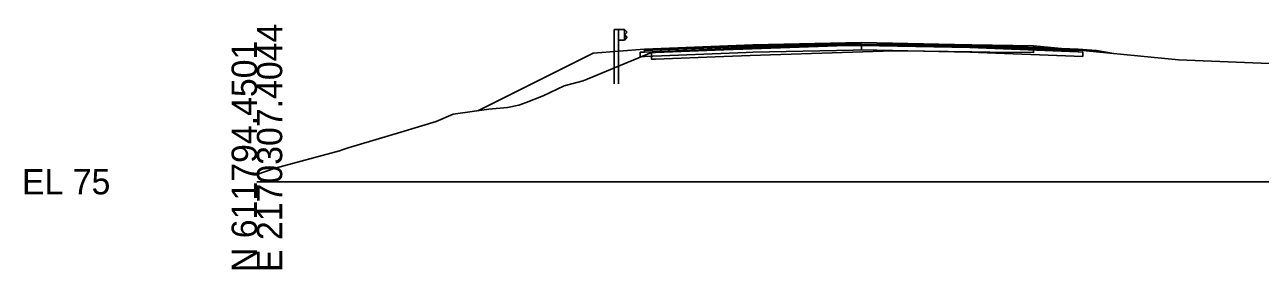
# Model space of a CAD drawing. Extents: x -26 to 1303, y -3010 to 12023.
# Drawn here: x 974.3 to 1111, y 1490.3 to 1517.4 of the extents above; entities that cross this region are included whole.
import ezdxf

# ---------------------------------------------------------------- set-up
doc = ezdxf.new("R2010")
doc.units = 0
for name, color, linetype in [('RD_GPK_XS_Cell', 7, 'Continuous'), ('RD_PD_Final_TrvlWay', 7, 'Continuous'), ('RD_XS_Base', 7, 'Continuous'), ('RD_XS_ExGround', 7, 'Continuous'), ('RD_XS_ExPaveRet', 7, 'Continuous'), ('RD_XS_GR', 7, 'Continuous'), ('RD_XS_Greenside', 7, 'Continuous'), ('RD_XS_Pave', 7, 'Continuous'), ('RD_XS_PaveOvlay_CP', 7, 'Continuous'), ('RD_XS_TieSlope', 7, 'Continuous')]:
    doc.layers.add(name, color=color, linetype=linetype)

msp = doc.modelspace()

# ---------------------------------------------------------------- linework, layer by layer
at = {"layer": 'RD_GPK_XS_Cell'}
msp.add_line((1000, 1500), (1150, 1500), dxfattribs=at)
at = {"layer": 'RD_PD_Final_TrvlWay'}
msp.add_lwpolyline([(1040.02, 1510.84), (1040.02, 1514.44), (1039.52, 1514.4), (1039.52, 1510.84)], dxfattribs=at)
at = {"layer": 'RD_XS_Base'}
for p, q in [((1054.89, 1514.84), (1054.14, 1514.81)), ((1065.98, 1515.06), (1054.89, 1514.84)), ((1066.89, 1515.08), (1065.98, 1515.06)), ((1066.89, 1515.22), (1066.89, 1515.23)), ((1066.89, 1515.23), (1066.89, 1515.18)), ((1066.89, 1515.08), (1066.89, 1515.23)), ((1066.89, 1515.23), (1066.89, 1515.23)), ((1066.89, 1515.23), (1066.89, 1515.23)), ((1066.89, 1515.23), (1066.89, 1514.58)), ((1066.89, 1515.08), (1066.89, 1515.22)), ((1066.89, 1515.18), (1066.89, 1514.58)), ((1066.89, 1515.04), (1066.89, 1515.08)), ((1066.89, 1514.58), (1066.89, 1515.08)), ((1066.89, 1515.08), (1066.89, 1515.08)), ((1066.89, 1515.08), (1066.89, 1515.08)), ((1066.89, 1515.08), (1066.89, 1515.08)), ((1078.89, 1514.84), (1066.89, 1515.08)), ((1066.89, 1514.58), (1066.89, 1515.04)), ((1090.89, 1514.36), (1078.89, 1514.84)), ((1042.86, 1514.35), (1042.39, 1514.33)), ((1042.39, 1514.33), (1042.39, 1514.31)), ((1042.39, 1514.31), (1042.39, 1513.83)), ((1042.39, 1513.83), (1042.86, 1513.85)), ((1042.89, 1514.35), (1042.86, 1514.35)), ((1042.86, 1513.85), (1042.89, 1513.85)), ((1054.14, 1514.81), (1042.89, 1514.35)), ((1042.89, 1513.85), (1054.14, 1514.31)), ((1054.14, 1514.31), (1054.89, 1514.34)), ((1054.89, 1514.34), (1065.98, 1514.56)), ((1065.98, 1514.56), (1066.89, 1514.58)), ((1066.89, 1514.58), (1066.89, 1514.58)), ((1066.89, 1514.58), (1066.89, 1514.58)), ((1066.89, 1514.58), (1078.89, 1514.34)), ((1078.89, 1514.34), (1091.39, 1513.84)), ((1080.89, 1514.76), (1080.89, 1514.76)), ((1080.89, 1514.26), (1080.89, 1514.26)), ((1091.39, 1514.34), (1090.89, 1514.36)), ((1090.89, 1514.36), (1090.89, 1514.36)), ((1091.39, 1513.84), (1091.39, 1514.34)), ((1091.39, 1514.34), (1091.39, 1514.34))]:
    msp.add_line(p, q, dxfattribs=at)
at = {"layer": 'RD_XS_ExGround'}
msp.add_lwpolyline([(1000, 1500.8), (1002.01, 1501.49), (1009.13, 1503.43), (1009.56, 1503.56), (1010.11, 1503.75), (1015.91, 1505.47), (1019.82, 1506.67), (1021.72, 1507.46), (1025.68, 1508.01), (1027.71, 1508.2), (1028.97, 1508.48), (1029.8, 1508.77), (1031.66, 1509.52), (1034.01, 1510.6), (1036.1, 1511.18), (1043.67, 1514.3), (1051.65, 1514.61), (1070.43, 1515.24), (1079.12, 1515.13), (1085.93, 1515.04), (1092.9, 1514.38), (1101.96, 1513.5), (1113.85, 1513.01)], dxfattribs=at)
at = {"layer": 'RD_XS_ExPaveRet'}
for points in [[(1085.93, 1515.04), (1085.93, 1515.04), (1085.93, 1514.89), (1085.93, 1514.29), (1085.93, 1514.29), (1085.93, 1514.29), (1081.1, 1514.35), (1079.12, 1514.38), (1071.29, 1514.48), (1070.43, 1514.49), (1054.59, 1513.96), (1051.65, 1513.86), (1044.1, 1513.56), (1043.67, 1513.55), (1043.67, 1514.22), (1043.67, 1514.3), (1044.1, 1514.31), (1051.65, 1514.61), (1054.59, 1514.71), (1070.43, 1515.24), (1071.29, 1515.23), (1079.12, 1515.13), (1081.1, 1515.1), (1085.93, 1515.04), (1085.93, 1515.04)], [(1081.1, 1515.1), (1079.12, 1515.13), (1071.29, 1515.23), (1070.43, 1515.24), (1054.59, 1514.71), (1051.65, 1514.61), (1044.1, 1514.31), (1043.67, 1514.3), (1043.67, 1514.22), (1043.67, 1513.55), (1044.1, 1513.56), (1051.65, 1513.86), (1054.59, 1513.96), (1070.43, 1514.49), (1071.29, 1514.48), (1079.12, 1514.38), (1081.1, 1514.35), (1085.93, 1514.29), (1085.93, 1514.89), (1085.93, 1515.04), (1081.1, 1515.1)]]:
    msp.add_lwpolyline(points, dxfattribs=at)
at = {"layer": 'RD_XS_GR'}
for p, q in [((1039.52, 1514.4), (1039.52, 1516.84)), ((1039.52, 1516.84), (1039.77, 1516.84)), ((1039.77, 1516.84), (1040.02, 1516.84)), ((1040.02, 1516.84), (1040.02, 1514.44)), ((1040.02, 1515.67), (1040.02, 1516.84)), ((1040.02, 1516.84), (1040.69, 1516.84)), ((1040.69, 1516.84), (1040.69, 1515.67)), ((1040.7, 1516.82), (1040.69, 1516.84)), ((1040.69, 1516.84), (1040.69, 1516.78)), ((1040.69, 1516.78), (1040.69, 1515.67)), ((1040.69, 1516.26), (1040.95, 1516.53)), ((1040.7, 1516.24), (1040.69, 1516.26)), ((1040.96, 1516.55), (1040.7, 1516.82)), ((1040.96, 1515.96), (1040.7, 1516.24)), ((1040.95, 1516.53), (1040.96, 1516.55)), ((1040.69, 1515.67), (1040.02, 1515.67)), ((1040.69, 1515.67), (1040.95, 1515.95)), ((1040.95, 1515.95), (1040.96, 1515.96)), ((1040.02, 1514.44), (1039.52, 1514.4))]:
    msp.add_line(p, q, dxfattribs=at)
at = {"layer": 'RD_XS_Greenside'}
for p, q in [((1037.21, 1514.22), (1024.45, 1507.84)), ((1092.89, 1514.51), (1094.81, 1514.19))]:
    msp.add_line(p, q, dxfattribs=at)
at = {"layer": 'RD_XS_Pave'}
for p, q in [((1054.14, 1515.12), (1042.89, 1514.67)), ((1054.14, 1514.96), (1042.89, 1514.51)), ((1042.89, 1514.51), (1054.14, 1514.96)), ((1054.89, 1515.15), (1054.14, 1515.12)), ((1054.89, 1514.99), (1054.14, 1514.96)), ((1054.14, 1514.96), (1054.89, 1514.99)), ((1054.14, 1514.81), (1054.89, 1514.84)), ((1065.98, 1515.38), (1054.89, 1515.15)), ((1065.98, 1515.22), (1054.89, 1514.99)), ((1054.89, 1514.99), (1065.98, 1515.22)), ((1054.89, 1514.84), (1065.98, 1515.06)), ((1066.89, 1515.39), (1065.98, 1515.38)), ((1066.89, 1515.23), (1065.98, 1515.22)), ((1065.98, 1515.22), (1066.89, 1515.23)), ((1065.98, 1515.06), (1066.89, 1515.08)), ((1078.89, 1515.15), (1066.89, 1515.39)), ((1066.89, 1515.39), (1066.89, 1515.39)), ((1066.89, 1515.39), (1066.89, 1515.39)), ((1066.89, 1515.22), (1066.89, 1515.23)), ((1066.89, 1515.23), (1066.89, 1515.22)), ((1066.89, 1515.08), (1066.89, 1515.23)), ((1066.89, 1515.23), (1066.89, 1515.23)), ((1066.89, 1515.23), (1066.89, 1515.23)), ((1066.89, 1515.23), (1066.89, 1515.23)), ((1066.89, 1515.23), (1066.89, 1515.23)), ((1066.89, 1515.23), (1078.89, 1514.99)), ((1078.89, 1514.99), (1066.89, 1515.23)), ((1066.89, 1515.23), (1066.89, 1515.23)), ((1066.89, 1515.23), (1066.89, 1515.23)), ((1066.89, 1515.23), (1066.89, 1515.08)), ((1066.89, 1515.08), (1066.89, 1515.22)), ((1066.89, 1515.22), (1066.89, 1515.08)), ((1066.89, 1515.08), (1066.89, 1515.08)), ((1066.89, 1515.08), (1066.89, 1515.08)), ((1066.89, 1515.08), (1078.89, 1514.84)), ((1090.89, 1514.67), (1078.89, 1515.15)), ((1078.89, 1514.99), (1090.89, 1514.51)), ((1090.89, 1514.51), (1078.89, 1514.99)), ((1078.89, 1514.84), (1090.89, 1514.36)), ((1080.89, 1515.07), (1080.89, 1515.07)), ((1080.89, 1514.91), (1080.89, 1514.91)), ((1080.89, 1514.91), (1080.89, 1514.91)), ((1042.89, 1514.35), (1054.14, 1514.81)), ((1042.89, 1514.67), (1042.89, 1514.66)), ((1042.89, 1514.66), (1042.89, 1514.51)), ((1042.89, 1514.51), (1042.89, 1514.51)), ((1042.89, 1514.51), (1042.89, 1514.35)), ((1080.89, 1514.76), (1080.89, 1514.76)), ((1090.89, 1514.51), (1090.89, 1514.67)), ((1090.89, 1514.67), (1090.89, 1514.67)), ((1090.89, 1514.36), (1090.89, 1514.51)), ((1090.89, 1514.51), (1090.89, 1514.51))]:
    msp.add_line(p, q, dxfattribs=at)
at = {"layer": 'RD_XS_PaveOvlay_CP'}
for p, q in [((1042.89, 1514.67), (1054.89, 1515.15)), ((1054.89, 1515.15), (1066.89, 1515.39)), ((1066.89, 1515.39), (1078.89, 1515.15)), ((1078.89, 1515.15), (1090.89, 1514.67))]:
    msp.add_line(p, q, dxfattribs=at)
at = {"layer": 'RD_XS_TieSlope'}
for p, q in [((1042.89, 1514.67), (1037.21, 1514.22)), ((1090.89, 1514.67), (1092.89, 1514.51))]:
    msp.add_line(p, q, dxfattribs=at)

# ---------------------------------------------------------------- texts
at = {"layer": 'RD_GPK_XS_Cell'}
for s, p in [('E 2170307.4044', (1002.8, 1490)), ('N 611794.4501', (1000, 1490))]:
    msp.add_text(s, height=2.8, rotation=90, dxfattribs=at).set_placement(p)
msp.add_text('EL 75', height=2.8, dxfattribs=at).set_placement((974, 1498.6))

doc.saveas('drawing.dxf')
